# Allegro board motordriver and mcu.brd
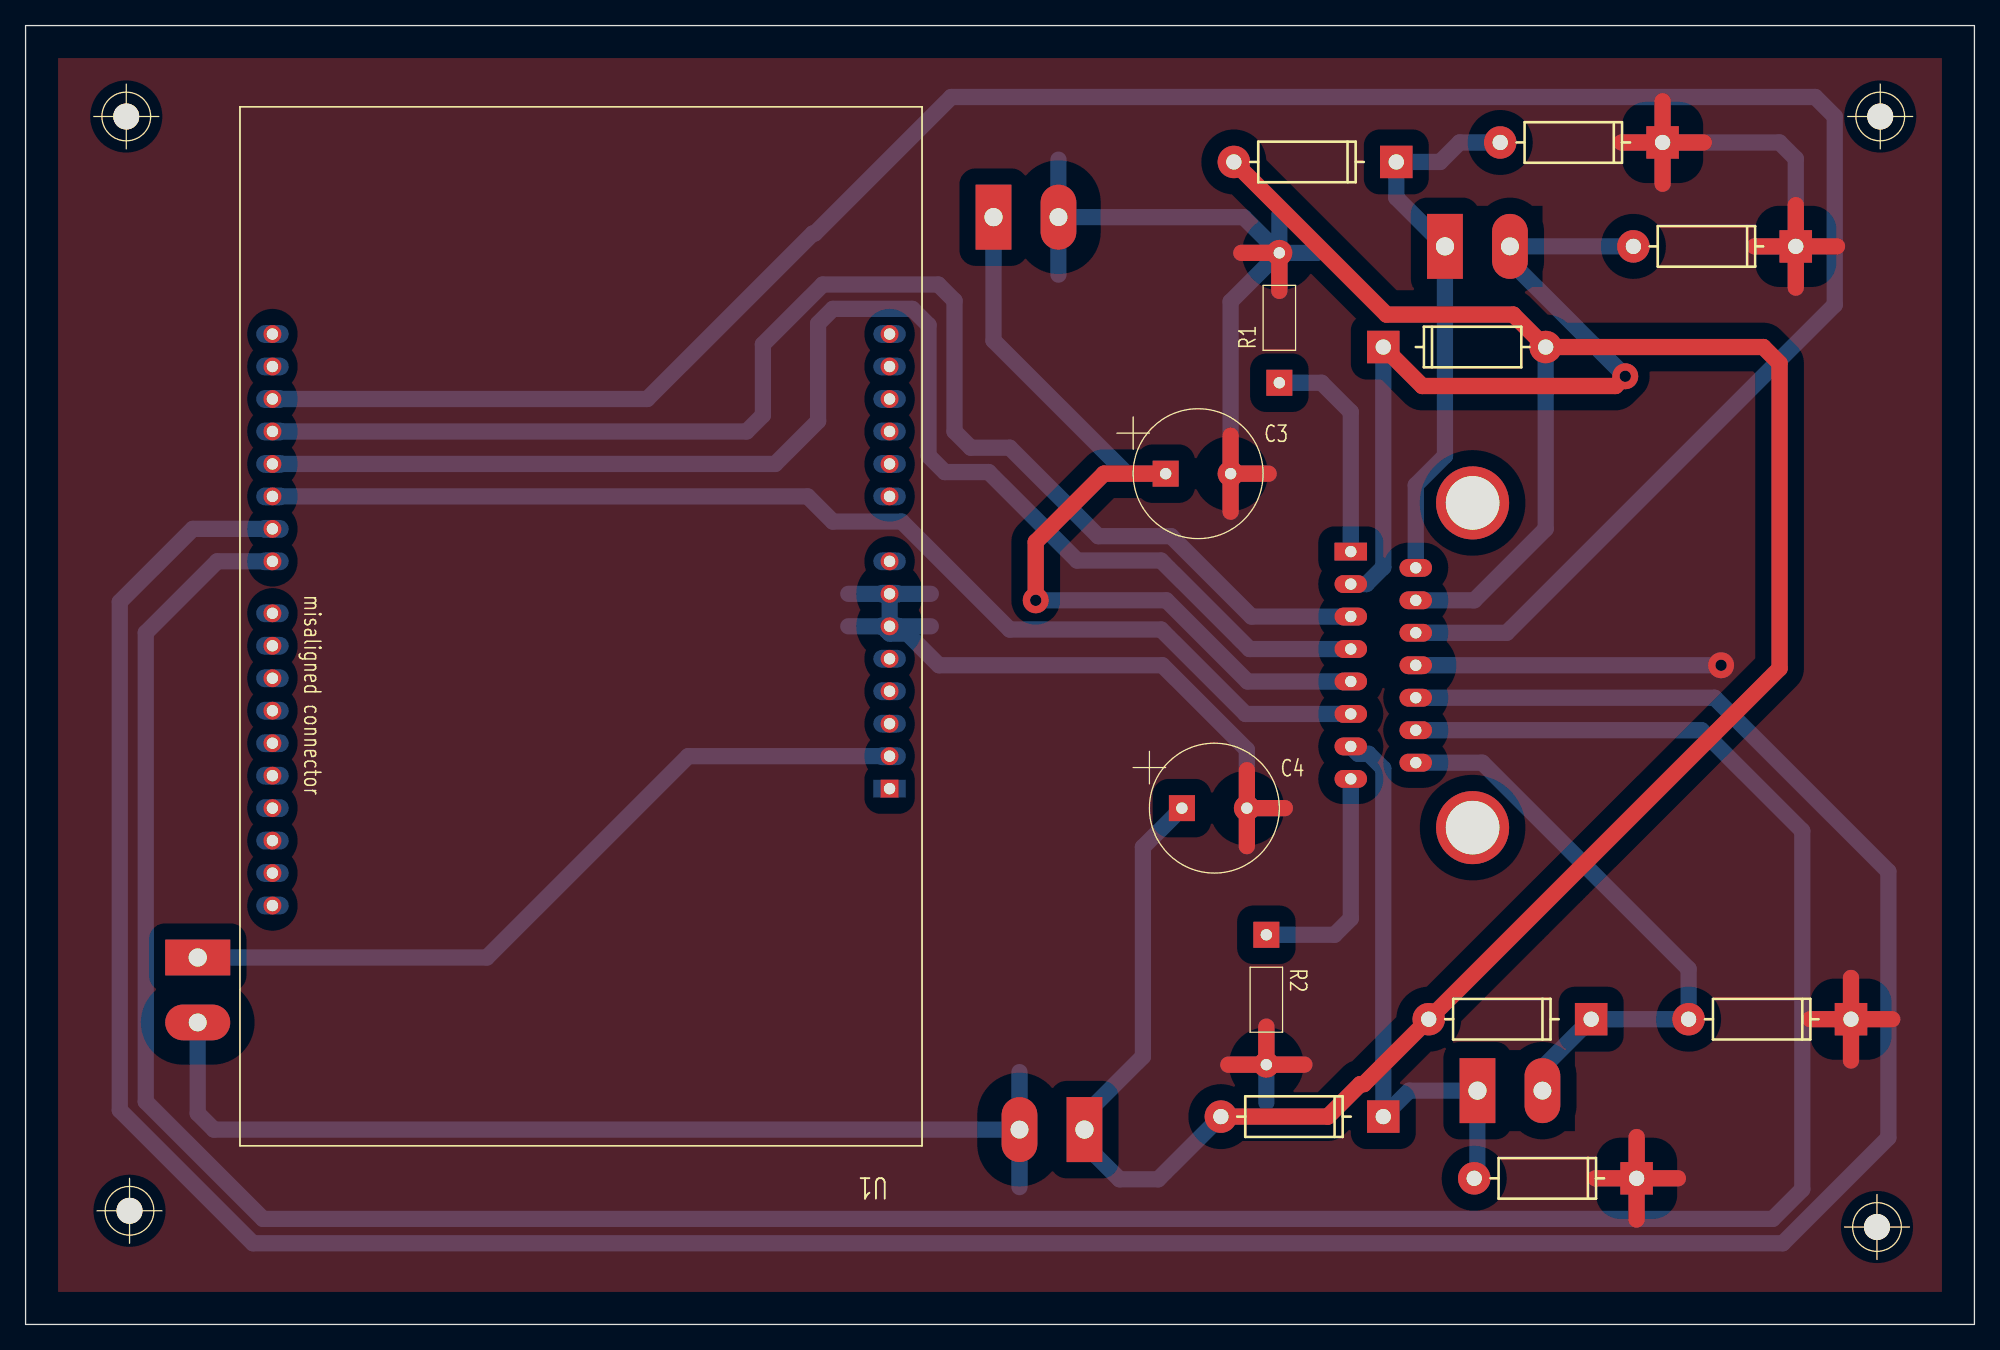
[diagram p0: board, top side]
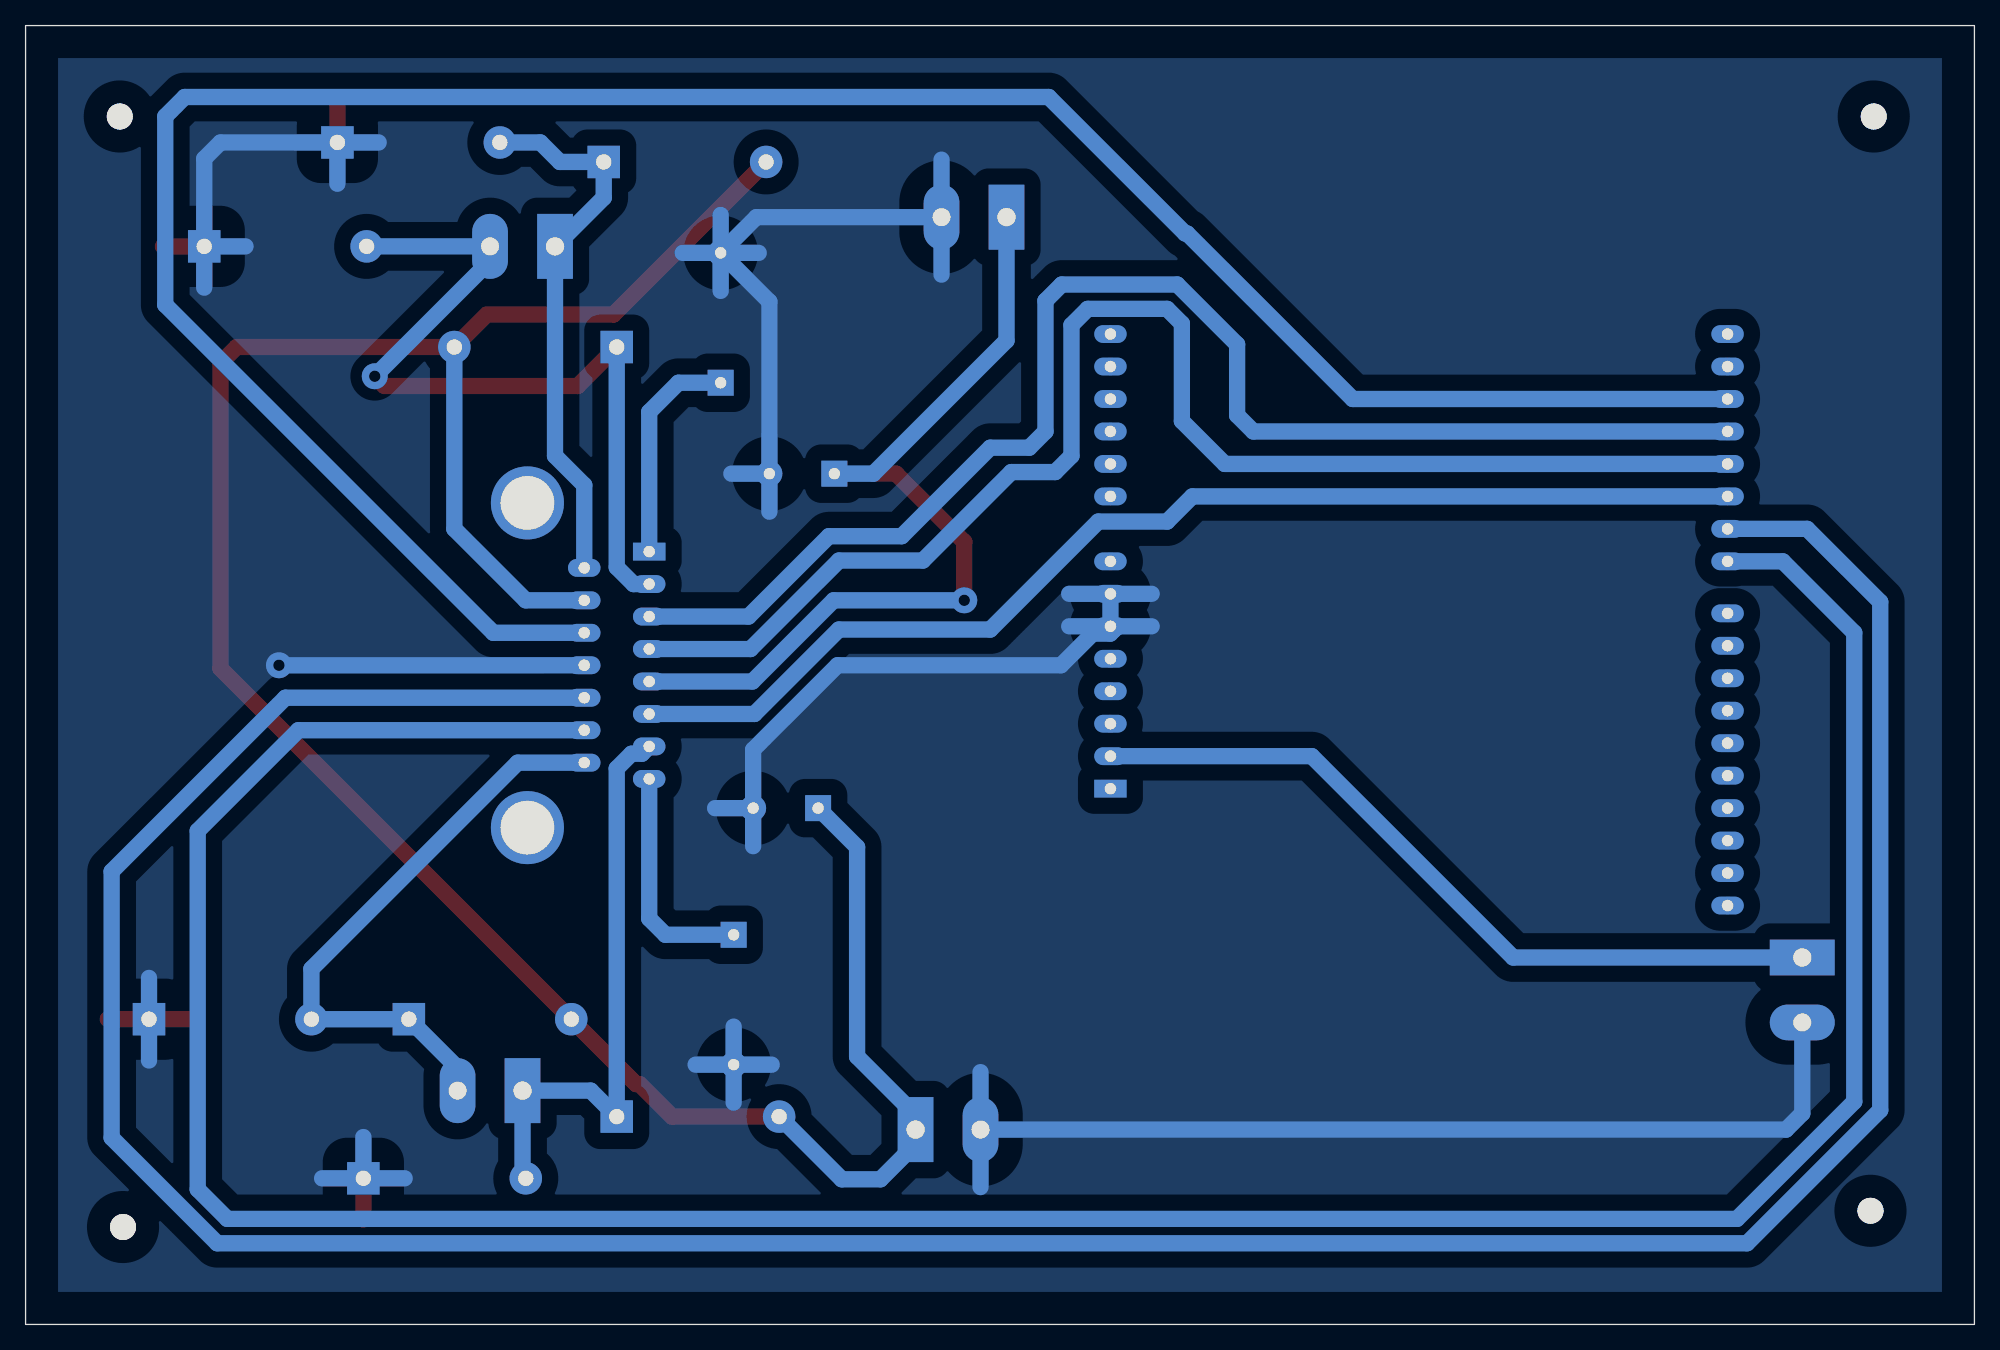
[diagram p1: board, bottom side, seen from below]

Outline 152.4 x 101.6 mm; copper layers: TOP, BOTTOM. Coordinates in mm from the lower left corner of the outline.
Outline path: rectangle 0,0 152.4,101.6

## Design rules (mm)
constraint set DEFAULT: min track width 1.27

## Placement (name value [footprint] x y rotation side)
C3  CAP POL  [GU-CAPCYL200]  89.15 66.55 0 top
C4  CAP POL  [GU-CAPCYL200]  90.42 40.39 0 top
D1  DIODE  [GU-1N4001]  107.19 90.93 180 top
D2  DIODE  [GU-1N4001]  128.02 92.46 180 top
D3  DIODE  [GU-1N4001]  106.17 76.45 0 top
D4  DIODE  [GU-1N4001]  138.43 84.33 180 top
D5  DIODE  [GU-1N4001]  106.17 16.26 180 top
D6  DIODE  [GU-1N4001]  125.98 11.43 180 top
D7  DIODE  [GU-1N4001]  122.43 23.88 180 top
D8  DIODE  [GU-1N4001]  142.75 23.88 180 top
J1  CON2  [GU-TERMINAL2-200]  13.46 28.7 0 top
J2  CON2  [GU-TERMINAL2-200]  82.8 15.24 270 top
J3  CON2  [GU-TERMINAL2-200]  75.69 86.61 90 top
J4  CON2  [GU-TERMINAL2-200]  111 84.33 90 top
J5  CON2  [GU-TERMINAL2-200]  113.54 18.29 90 top
NOREF  -  [unnamed]  7.87 94.49 0 top
NOREF#2  -  [unnamed]  8.13 8.89 0 top
NOREF#3  -  [unnamed]  145.03 94.49 0 top
NOREF#4  -  [unnamed]  144.78 7.62 0 top
R1  1  [GU-RC400]  98.04 73.66 90 top
R2  1  [GU-RC400]  97.03 30.48 270 top
U1  FRDM-KL25Z-Arduino  [GU-FRDM-ARDUINO]  67.56 41.91 180 top
U2  L298/MUTIV  [GU-L298-HSINK2]  103.63 60.45 270 top

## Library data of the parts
C3 C4 = CAP POL
D1-D8 = DIODE
J1-J5 = CON2: User Part Number: TERMINAL2-200
R1 R2 = R
U1 = FRDM-KL25Z-Arduino
U2 = L298/MUTIV_0

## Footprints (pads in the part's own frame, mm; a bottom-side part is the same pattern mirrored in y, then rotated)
GU-1N4001
  round 2.54 hole 1.194: 1(12.7,0)
  rect 2.54x2.54 hole 1.194: 2(0,0)
GU-CAPCYL200
  rect 2.032x2.032 hole 0.889: 1(0,0)
  round 2.032 hole 0.889: 2(5.08,0)
GU-FRDM-ARDUINO
  rect 1.397x1.397 hole 0.889: 1(0,0)
  round 1.397 hole 0.889: 2(0,-2.54) 3(0,-5.08) 4(0,-7.62) 5(0,-10.16) 6(0,-12.7) 7(0,-15.24) 8(0,-17.78) 9(0,-22.86) 10(0,-25.4) 11(0,-27.94) 12(0,-30.48) 13(0,-33.02) 14(0,-35.56) 15(48.26,-35.56) 16(48.26,-33.02) 17(48.26,-30.48) 18(48.26,-27.94) 19(48.26,-25.4) 20(48.26,-22.86) 21(48.26,-20.32) 22(48.26,-17.78) 23(48.26,-13.716) 24(48.26,-11.176) 25(48.26,-8.636) 26(48.26,-6.096) 27(48.26,-3.556) 28(48.26,-1.016) 29(48.26,1.524) 30(48.26,4.064) 31(48.26,6.604) 32(48.26,9.144)
GU-L298-HSINK2
  round 5.715 hole 4.191 unplated: (-3.81,9.525) (21.59,9.525)
  rect 1.397x2.54 hole 0.889: 1(0,0)
  oval 1.397x2.54 hole 0.889: 2(1.27,5.08) 3(2.54,0) 4(3.81,5.08) 5(5.08,0) 6(6.35,5.08) 7(7.62,0) 8(8.89,5.08) 9(10.16,0) 10(11.43,5.08) 11(12.7,0) 12(13.97,5.08) 13(15.24,0) 14(16.51,5.08) 15(17.78,0)
GU-RC400
  rect 2.032x2.032 hole 0.889: 1(0,0)
  round 2.032 hole 0.889: 2(10.16,0)
GU-TERMINAL2-200
  rect 5.08x2.794 hole 1.422: 1(0,0)
  oval 5.08x2.794 hole 1.397: 2(0,-5.08)
unnamed
  round 2.032 hole 3.962 unplated: (0,0)

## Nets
3V3: C3.1 J3.1 U2.9(VSS)
12V: C4.1 D1.1(K) D3.1(K) D5.1(K) D7.1(K) J2.1 U2.4
GND: C3.2 C4.2 D2.2 D4.2 D6.2 D8.2 J1.2 J2.2 J3.2 R1.2 R2.2 U1.6 U1.7 U2.8
EN A: U1.17 U2.6
EN B: U1.20 U2.11
IN 1: U1.18 U2.5
IN 2: U1.19 U2.7
IN 3: U1.21 U2.10
IN 4: U1.22 U2.12
OUT 1: D1.2 D2.1(K) J4.1 U2.2
OUT 2: D3.2 D4.1(K) J4.2 U2.3
OUT 3: D5.2 D6.1(K) J5.1 U2.13
OUT 4: D7.2 D8.1(K) J5.2 U2.14
N00758: J1.1 U1.2
N01131: R1.1 U2.1
N01135: R2.1 U2.15

Pads without a net: U1 1 3 4 5 8 9 10 11 12 13 14 15 16 23 24 25 26 27 28 29 30 31 32

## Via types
v1: diameter 2.032, hole 0.889, TOP to BOTTOM, 3 vias

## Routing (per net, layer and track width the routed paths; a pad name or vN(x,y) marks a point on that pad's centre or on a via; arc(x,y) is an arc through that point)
3V3: length 71.6
  TOP w1.27: C3.1 84.33,66.55 78.99,61.21 v1(78.99,56.64)
  BOTTOM w1.27: C3.1 86.11,66.55 75.69,76.96 J3.1 ; v1(78.99,56.64) 89.21,56.64 95.56,50.29 U2.9
12V: length 201.3
  TOP w1.27: D5.1 101.84,16.26 104.38,18.8 104.65,18.8 D7.1 137.16,51.31 137.16,75.18 135.89,76.45 D3.1 116.33,78.99 106.43,78.99 D1.1
  BOTTOM w1.27: D3.1 118.87,62.23 113.28,56.64 U2.4 ; C4.1 87.38,37.34 87.38,20.95 82.8,16.38 J2.1 82.8,14.1 85.55,11.35 88.57,11.35 D5.1
GND: length 370.4
  TOP w1.27: R2.2 100,20.32 ; R2.2 94.06,20.32 ; R2.2 97.03,23.29 ; 142.75,20.65 D8.2 ; D8.2 142.75,27.1 ; D8.2 145.97,23.88 ; D8.2 139.52,23.88 ; D6.2 129.21,11.43 ; D6.2 125.98,14.66 ; D6.2 122.76,11.43 ; D6.2 125.98,8.2 ; C4.2 98.48,40.39 ; C4.2 95.5,43.36 ; C4.2 95.5,37.41 ; D4.2 138.43,87.55 ; D4.2 135.2,84.33 ; D4.2 138.43,81.1 ; D4.2 141.66,84.33 ; 98.04,80.85 R1.2 95.07,83.82 ; 94.23,63.58 C3.2 ; C3.2 97.21,66.55 ; C3.2 94.23,69.52 ; 124.79,92.46 D2.2 ; D2.2 131.24,92.46 ; D2.2 128.02,95.68 ; D2.2 128.02,89.23
  BOTTOM w1.27: J2.2 77.72,19.74 ; J2.2 14.73,15.24 13.46,16.51 J1.2 ; J2.2 77.72,10.74 ; R2.2 97.03,23.29 ; R2.2 94.06,20.32 ; R2.2 97.03,17.35 ; R2.2 100,20.32 ; D4.2 138.43,91.19 137.16,92.46 D2.2 ; D4.2 135.2,84.33 ; D4.2 138.43,81.1 ; D6.2 129.21,11.43 ; D6.2 122.76,11.43 ; D6.2 125.98,14.66 ; R1.2 94.23,80.01 C3.2 ; R1.2 98.04,80.85 ; R1.2 95.25,86.61 J3.2 ; R1.2 101.02,83.82 ; R1.2 98.04,86.79 ; R1.2 95.07,83.82 ; 94.23,63.58 C3.2 ; C3.2 97.21,66.55 ; J3.2 80.77,82.12 ; J3.2 80.77,91.11 ; U1.7 U1.6 ; U1.7 70.79,57.15 ; U1.7 64.34,57.15 ; U1.6 67.28,54.33 67.57,54.04 68.95,54.04 71.43,51.56 88.9,51.56 95.5,44.96 C4.2 ; U1.6 64.34,54.61 ; U1.6 70.79,54.61 ; 142.75,20.65 D8.2 142.75,27.1 ; 128.02,89.23 D2.2 ; D2.2 124.79,92.46 ; 95.5,37.41 C4.2 ; C4.2 98.48,40.39 ; U2.8 v1(132.59,51.56)
EN A: length 190.7
  BOTTOM w1.27: U1.17 48.61,72.39 61.56,85.33 61.71,85.33 72.39,96.01 139.95,96.01 141.48,94.49 141.48,79.76 115.82,54.1 U2.6
EN B: length 91.4
  BOTTOM w1.27: U2.11 95.4,47.75 88.8,54.36 76.96,54.36 68.52,62.8 63.13,62.8 61.16,64.77 U1.20
IN 1: length 109.1
  BOTTOM w1.27: U1.18 56.39,69.85 57.66,71.12 57.66,76.66 62.34,81.34 71.37,81.34 72.64,80.07 72.64,69.85 73.91,68.58 76.96,68.58 83.88,61.66 89.58,61.66 95.87,55.37 U2.5
IN 2: length 110.8
  BOTTOM w1.27: U1.19 58.62,67.31 61.98,70.67 61.98,78.29 63.13,79.44 69.34,79.44 70.61,78.17 70.61,67.94 71.88,66.67 75.31,66.67 82.23,59.75 88.79,59.75 95.71,52.83 U2.7
IN 3: length 263.5
  BOTTOM w1.27: U1.21 13.08,62.23 7.37,56.52 7.37,16.76 17.78,6.35 137.41,6.35 145.67,14.6 145.67,35.43 132.08,49.02 U2.10
IN 4: length 244.7
  BOTTOM w1.27: U1.22 14.99,59.69 9.4,54.1 9.4,17.43 18.57,8.25 136.62,8.25 138.94,10.57 138.94,38.61 131.06,46.48 U2.12
OUT 1: length 43
  BOTTOM w1.27: U2.2 108.71,65.65 111,67.94 J4.1 107.19,88.14 D1.2 110.62,90.93 112.14,92.46 D2.1
OUT 2: length 64.4
  TOP w1.27: D3.2 109.22,73.41 124.33,73.41 v1(125.09,74.17)
  BOTTOM w1.27: U2.3 104.86,57.91 106.17,59.23 D3.2 ; D4.1 J4.2 116.08,83.19 v1(125.09,74.17)
OUT 3: length 45.7
  BOTTOM w1.27: U2.13 104.2,44.64 105.02,44.64 106.17,43.49 D5.2 108.2,18.29 J5.1 113.54,11.68 D6.1
OUT 4: length 46.7
  BOTTOM w1.27: J5.2 118.62,20.07 D7.2 D8.1 130.05,27.81 113.91,43.94 U2.14
N00758: length 60.6
  BOTTOM w1.27: U1.2 51.82,44.45 36.07,28.7 J1.1
N01131: length 17.5
  BOTTOM w1.27: U2.1 103.63,71.37 101.35,73.66 R1.1
N01135: length 18.1
  BOTTOM w1.27: R2.1 102.36,30.48 103.63,31.75 U2.15

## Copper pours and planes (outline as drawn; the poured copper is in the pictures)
GND on TOP: 2.54,99.06 149.86,99.06 149.86,2.54 2.54,2.54 ; 2 cut-outs
GND on BOTTOM: 2.54,99.06 149.86,99.06 149.86,2.54 2.54,2.54 ; 10 cut-outs
